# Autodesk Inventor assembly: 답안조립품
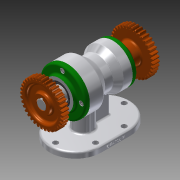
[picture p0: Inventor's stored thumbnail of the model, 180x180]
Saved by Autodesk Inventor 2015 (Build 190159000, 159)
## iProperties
Created: 2020-01
Part Number: 답안조립품
Document SubType Name: Assembly
Designer: LINEART-SSD.D4.16.05
Author: LINEART-SSD.D4.16.05
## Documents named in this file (13)
- C:\Users\LINEART-SSD.D4.16.05\Desktop\700104V1025\답안조립품.iam
- C:\Users\LINEART-SSD.D4.16.05\Desktop\700104V1025\본체.ipt
- C:\Users\LINEART-SSD.D4.16.05\Desktop\700104V1025\베어링 6205.ipt
- C:\Users\LINEART-SSD.D4.16.05\Desktop\700104V1025\베어링 6203.ipt
- C:\Users\LINEART-SSD.D4.16.05\Desktop\700104V1025\앞커버.ipt
- C:\Users\LINEART-SSD.D4.16.05\Desktop\700104V1025\뒤커버.ipt
- C:\Users\LINEART-SSD.D4.16.05\Desktop\700104V1025\볼트 M4.ipt
- C:\Users\LINEART-SSD.D4.16.05\Desktop\700104V1025\축.ipt
- C:\Users\LINEART-SSD.D4.16.05\Desktop\700104V1025\오일 실 25 38 8.ipt
- C:\Users\LINEART-SSD.D4.16.05\Desktop\700104V1025\오일 실 17 30 8.ipt
- C:\Users\LINEART-SSD.D4.16.05\Desktop\700104V1025\키 5 x 5 x 18.ipt
- C:\Users\LINEART-SSD.D4.16.05\Desktop\700104V1025\스퍼기어.ipt
- C:\Users\LINEART-SSD.D4.16.05\Desktop\700104V1025\멈춤나사 M3.ipt
